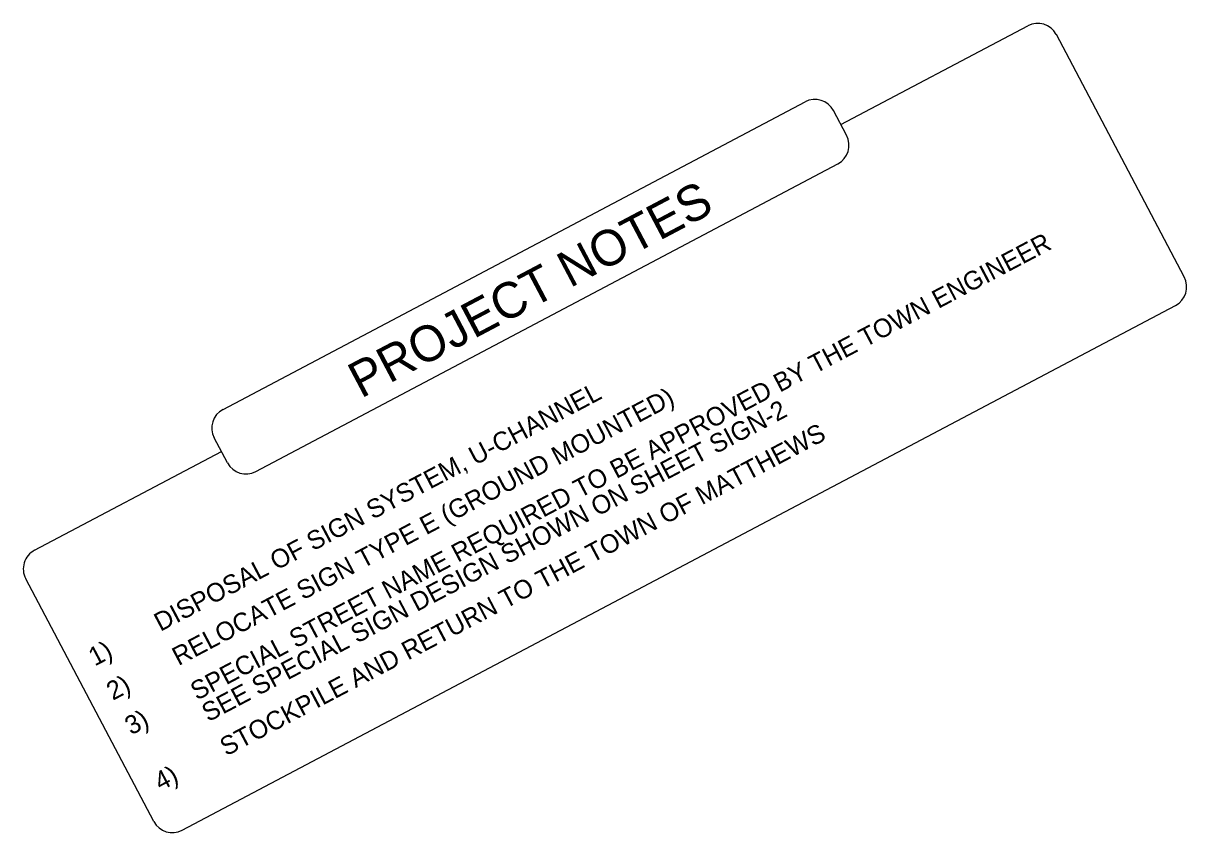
# Model space of a CAD drawing. Extents: x 1487362 to 2061618, y 497428 to 671257.
# Drawn here: x 1487588.7 to 1488039.9, y 498870.3 to 499184.1 of the extents above; entities that cross this region are included whole.
import ezdxf

# ---------------------------------------------------------------- set-up
doc = ezdxf.new("R2010")
doc.units = 0
for name, color, linetype in [('Default', 7, 'Continuous'), ('Sheet Title CELL', 7, 'Continuous'), ('Text', 7, 'Continuous')]:
    doc.layers.add(name, color=color, linetype=linetype)

msp = doc.modelspace()

# ---------------------------------------------------------------- linework, layer by layer
at = {"layer": 'Sheet Title CELL'}
for p, q in [((1487905.8, 499144.85), (1487978.31, 499183.14)), ((1488038.99, 499085.74), (1487989.37, 499179.73)), ((1487666.17, 499034.44), (1487891.9, 499153.63)), ((1487908.01, 499140.67), (1487902.95, 499150.23)), ((1487678.93, 499010.3), (1487904.6, 499129.61)), ((1487650.35, 498871.27), (1488035.58, 499074.68)), ((1487667.88, 499013.71), (1487662.76, 499023.39)), ((1487593.05, 498979.79), (1487665.57, 499018.08)), ((1487639.3, 498874.69), (1487589.64, 498968.74))]:
    msp.add_line(p, q, dxfattribs=at)
for centre, start, end in [((1487982.13, 499175.91), 27.8351, 117.8351), ((1487895.72, 499146.4), 27.8652, 117.8652), ((1487900.78, 499136.84), 297.8652, 27.8652), ((1488031.76, 499081.92), 297.8351, 27.8351), ((1487669.99, 499027.21), 117.8652, 207.8652), ((1487675.11, 499017.54), 207.8652, 297.8652), ((1487596.87, 498972.56), 117.8351, 207.8351), ((1487646.53, 498878.51), 207.8351, 297.8351)]:
    msp.add_arc(centre, 8.18, start, end, dxfattribs=at)

# ---------------------------------------------------------------- texts
at = {"layer": 'Default'}
msp.add_text('PROJECT NOTES', height=13.8661, rotation=27.8652, dxfattribs=at).set_placement((1487719.69, 499038.52))
at = {"layer": 'Text'}
for s, height, p in [('SPECIAL STREET NAME REQUIRED TO BE APPROVED BY THE TOWN ENGINEER', 7.1994, (1487655.99, 498921.46)), ('DISPOSAL OF SIGN SYSTEM, U-CHANNEL', 7.1994, (1487641.89, 498948.16)), ('RELOCATE SIGN TYPE E (GROUND MOUNTED)', 7.1994, (1487648.9, 498934.9)), ('SEE SPECIAL SIGN DESIGN SHOWN ON SHEET SIGN-2 ', 7.1994, (1487660.4, 498913.11)), ('STOCKPILE AND RETURN TO THE TOWN OF MATTHEWS', 7.1994, (1487667.41, 498899.85)), ('1)', 7.199, (1487616.43, 498934.72)), ('2)', 7.199, (1487623.43, 498921.45)), ('3)', 7.199, (1487630.53, 498908.01)), ('4)', 7.199, (1487641.94, 498886.4))]:
    msp.add_text(s, height=height, rotation=27.8351, dxfattribs=at).set_placement(p)

doc.saveas('drawing.dxf')
